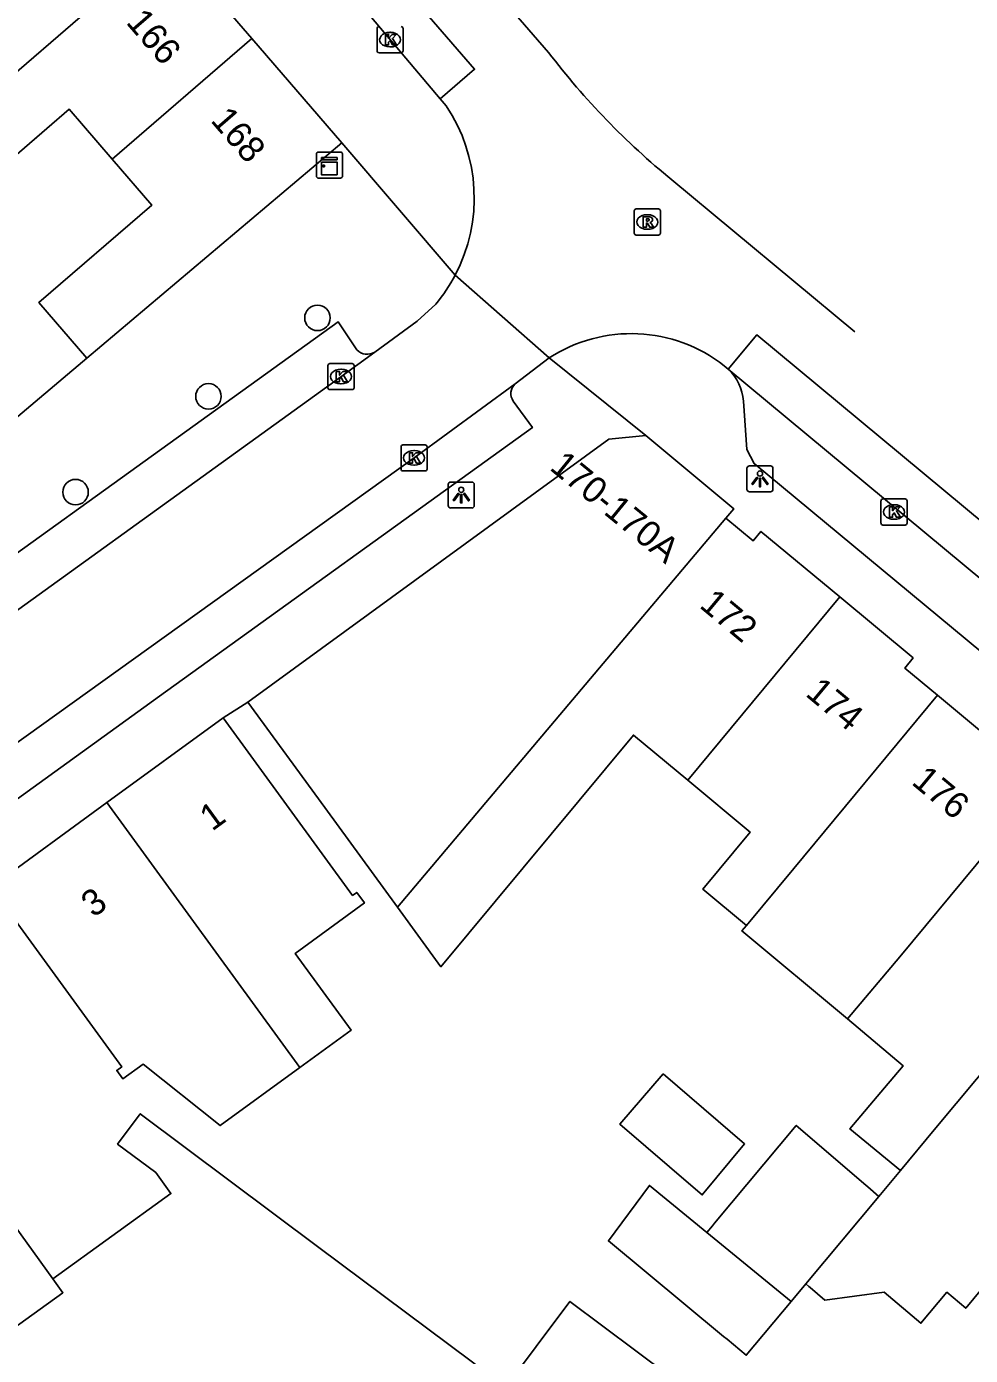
# Model space of a CAD drawing. Extents: x 161882 to 162509, y 381687 to 382379.
# Drawn here: x 162311.3 to 162347.5, y 381930 to 381980.9 of the extents above; entities that cross this region are included whole.
import ezdxf

# ---------------------------------------------------------------- set-up
doc = ezdxf.new("R2010")
doc.units = 0
for name, color, linetype in [('IMGEO_Boom', 7, 'Continuous'), ('IMGEO_Kast', 7, 'Continuous'), ('IMGEO_Kolk', 7, 'Continuous'), ('IMGEO_Lichtpunt', 7, 'Continuous'), ('IMGEO_Muur', 7, 'Continuous'), ('IMGEO_Pand', 7, 'Continuous'), ('IMGEO_Pand_nummerreeks', 7, 'Continuous'), ('IMGEO_Rijbaan_lokaal_gesloten', 7, 'Continuous'), ('IMGEO_Rijbaan_lokaal_open', 7, 'Continuous'), ('IMGEO_Rioolput', 7, 'Continuous'), ('IMGEO_Voetpad_open', 7, 'Continuous')]:
    doc.layers.add(name, color=color, linetype=linetype)

msp = doc.modelspace()

# ---------------------------------------------------------------- linework, layer by layer
at = {"layer": 'IMGEO_Boom'}
for centre in [(162322.501, 381969.752), (162318.322, 381966.743), (162313.226, 381963.073)]:
    msp.add_circle(centre, 0.489, dxfattribs=at)
at = {"layer": 'IMGEO_Kast'}
for p, q in [((162322.46, 381975.185), (162322.46, 381976.026)), ((162322.46, 381976.026), (162322.46, 381975.185)), ((162322.535, 381976.11), (162323.376, 381976.11)), ((162323.376, 381976.11), (162322.535, 381976.11)), ((162323.46, 381976.035), (162323.46, 381975.194)), ((162323.46, 381975.194), (162323.46, 381976.035)), ((162323.385, 381975.11), (162322.544, 381975.11)), ((162322.544, 381975.11), (162323.385, 381975.11))]:
    msp.add_line(p, q, dxfattribs=at)
for points in [[(162322.655, 381975.9), (162323.255, 381975.9), (162323.255, 381975.815), (162322.655, 381975.815), (162322.655, 381975.9)], [(162322.655, 381975.725), (162323.255, 381975.725), (162323.255, 381975.236), (162322.655, 381975.236), (162322.655, 381975.725)]]:
    msp.add_lwpolyline(points, dxfattribs=at)
msp.add_circle((162322.739, 381975.574), 0.0377, dxfattribs=at)
for centre, start, end in [((162322.538, 381976.032), 92.4484, 184.2845), ((162322.538, 381976.032), 92.4484, 184.2845), ((162323.382, 381976.032), 2.4484, 94.2845), ((162323.382, 381976.032), 2.4484, 94.2845), ((162322.538, 381975.188), 182.4484, 274.2845), ((162322.538, 381975.188), 182.4484, 274.2845), ((162323.382, 381975.188), 272.4484, 4.2845), ((162323.382, 381975.188), 272.4484, 4.2845)]:
    msp.add_arc(centre, 0.0779, start, end, dxfattribs=at)
at = {"layer": 'IMGEO_Kolk'}
for p, q in [((162324.785, 381979.992), (162324.785, 381980.844)), ((162325.786, 381980.844), (162325.786, 381979.992)), ((162325.273, 381980.698), (162325.298, 381980.698)), ((162325.712, 381979.918), (162324.86, 381979.918)), ((162325.296, 381980.138), (162325.271, 381980.138)), ((162322.903, 381967.077), (162322.903, 381967.929)), ((162322.978, 381968.003), (162323.83, 381968.003)), ((162323.391, 381967.783), (162323.416, 381967.783)), ((162323.904, 381967.929), (162323.904, 381967.077)), ((162323.414, 381967.223), (162323.389, 381967.223)), ((162323.83, 381967.003), (162322.978, 381967.003)), ((162325.704, 381963.959), (162325.704, 381964.811)), ((162325.779, 381964.885), (162326.631, 381964.885)), ((162326.192, 381964.665), (162326.217, 381964.665)), ((162326.705, 381964.811), (162326.705, 381963.959)), ((162326.215, 381964.105), (162326.19, 381964.105)), ((162326.631, 381963.885), (162325.779, 381963.885)), ((162344.107, 381961.886), (162344.107, 381962.738)), ((162344.182, 381962.812), (162345.034, 381962.812)), ((162344.595, 381962.592), (162344.62, 381962.592)), ((162345.108, 381962.738), (162345.108, 381961.886)), ((162344.618, 381962.032), (162344.593, 381962.032)), ((162345.034, 381961.812), (162344.182, 381961.812))]:
    msp.add_line(p, q, dxfattribs=at)
for points in [[(162324.785, 381979.992), (162324.785, 381980.844)], [(162325.786, 381980.844), (162325.786, 381979.992)], [(162325.106, 381980.618), (162325.229, 381980.618), (162325.229, 381980.467), (162325.359, 381980.618), (162325.523, 381980.618), (162325.377, 381980.467), (162325.53, 381980.218), (162325.378, 381980.218), (162325.293, 381980.382), (162325.229, 381980.315), (162325.229, 381980.218), (162325.106, 381980.218), (162325.106, 381980.618)], [(162325.712, 381979.918), (162324.86, 381979.918)], [(162322.903, 381967.077), (162322.903, 381967.929)], [(162322.978, 381968.003), (162323.83, 381968.003)], [(162323.224, 381967.703), (162323.347, 381967.703), (162323.347, 381967.552), (162323.477, 381967.703), (162323.641, 381967.703), (162323.495, 381967.552), (162323.648, 381967.303), (162323.496, 381967.303), (162323.411, 381967.467), (162323.347, 381967.4), (162323.347, 381967.303), (162323.224, 381967.303), (162323.224, 381967.703)], [(162323.904, 381967.929), (162323.904, 381967.077)], [(162323.83, 381967.003), (162322.978, 381967.003)], [(162325.704, 381963.959), (162325.704, 381964.811)], [(162325.779, 381964.885), (162326.631, 381964.885)], [(162326.025, 381964.585), (162326.148, 381964.585), (162326.148, 381964.434), (162326.278, 381964.585), (162326.442, 381964.585), (162326.296, 381964.434), (162326.449, 381964.185), (162326.297, 381964.185), (162326.212, 381964.349), (162326.148, 381964.282), (162326.148, 381964.185), (162326.025, 381964.185), (162326.025, 381964.585)], [(162326.705, 381964.811), (162326.705, 381963.959)], [(162326.631, 381963.885), (162325.779, 381963.885)], [(162344.107, 381961.886), (162344.107, 381962.738)], [(162344.182, 381962.812), (162345.034, 381962.812)], [(162344.428, 381962.512), (162344.551, 381962.512), (162344.551, 381962.361), (162344.681, 381962.512), (162344.845, 381962.512), (162344.699, 381962.361), (162344.852, 381962.112), (162344.7, 381962.112), (162344.615, 381962.276), (162344.551, 381962.209), (162344.551, 381962.112), (162344.428, 381962.112), (162344.428, 381962.512)], [(162345.108, 381962.738), (162345.108, 381961.886)], [(162345.034, 381961.812), (162344.182, 381961.812)]]:
    msp.add_lwpolyline(points, dxfattribs=at)
for centre, start, end in [((162324.862, 381980.842), 91.552, 178.448), ((162324.862, 381980.842), 91.552, 178.448), ((162325.71, 381980.842), 1.552, 88.448), ((162325.71, 381980.842), 1.552, 88.448), ((162324.862, 381979.994), 181.552, 268.448), ((162324.862, 381979.994), 181.552, 268.448), ((162325.71, 381979.994), 271.552, 358.448), ((162325.71, 381979.994), 271.552, 358.448), ((162322.98, 381967.927), 91.552, 178.448), ((162322.98, 381967.927), 91.552, 178.448), ((162323.828, 381967.927), 1.552, 88.448), ((162323.828, 381967.927), 1.552, 88.448), ((162322.98, 381967.079), 181.552, 268.448), ((162322.98, 381967.079), 181.552, 268.448), ((162323.828, 381967.079), 271.552, 358.448), ((162323.828, 381967.079), 271.552, 358.448), ((162325.781, 381964.809), 91.552, 178.448), ((162325.781, 381964.809), 91.552, 178.448), ((162326.629, 381964.809), 1.552, 88.448), ((162326.629, 381964.809), 1.552, 88.448), ((162325.781, 381963.961), 181.552, 268.448), ((162325.781, 381963.961), 181.552, 268.448), ((162326.629, 381963.961), 271.552, 358.448), ((162326.629, 381963.961), 271.552, 358.448), ((162344.184, 381962.736), 91.552, 178.448), ((162344.184, 381962.736), 91.552, 178.448), ((162345.032, 381962.736), 1.552, 88.448), ((162345.032, 381962.736), 1.552, 88.448), ((162344.184, 381961.888), 181.552, 268.448), ((162344.184, 381961.888), 181.552, 268.448), ((162345.032, 381961.888), 271.552, 358.448), ((162345.032, 381961.888), 271.552, 358.448)]:
    msp.add_arc(centre, 0.0765, start, end, dxfattribs=at)
for centre, major_axis, ratio, start_param, end_param in [((162325.272, 381980.418), (-0.387, 0.002), 0.722429, 4.712389, 7.853982), ((162325.297, 381980.418), (-0.39, 0.002), 0.717154, 1.570796, 4.712389), ((162323.39, 381967.503), (-0.387, 0.002), 0.722429, 4.712389, 7.853982), ((162323.415, 381967.503), (-0.39, 0.002), 0.717154, 1.570796, 4.712389), ((162326.191, 381964.385), (-0.387, 0.002), 0.722429, 4.712389, 7.853982), ((162326.216, 381964.385), (-0.39, 0.002), 0.717154, 1.570796, 4.712389), ((162344.594, 381962.312), (-0.387, 0.002), 0.722429, 4.712389, 7.853982), ((162344.619, 381962.312), (-0.39, 0.002), 0.717154, 1.570796, 4.712389)]:
    msp.add_ellipse(centre, major_axis=major_axis, ratio=ratio, start_param=start_param, end_param=end_param, dxfattribs=at)
at = {"layer": 'IMGEO_Lichtpunt'}
for p, q in [((162339.87, 381964.082), (162339.062, 381964.082)), ((162339.87, 381964.082), (162339.062, 381964.082)), ((162338.968, 381963.987), (162338.968, 381963.18)), ((162338.968, 381963.987), (162338.968, 381963.18)), ((162339.964, 381963.18), (162339.964, 381963.987)), ((162339.964, 381963.18), (162339.964, 381963.987)), ((162327.515, 381963.367), (162327.515, 381962.56)), ((162327.515, 381963.367), (162327.515, 381962.56)), ((162328.417, 381963.462), (162327.609, 381963.462)), ((162328.417, 381963.462), (162327.609, 381963.462)), ((162328.511, 381962.56), (162328.511, 381963.367)), ((162328.511, 381962.56), (162328.511, 381963.367)), ((162339.062, 381963.086), (162339.87, 381963.086)), ((162339.062, 381963.086), (162339.87, 381963.086)), ((162327.609, 381962.466), (162328.417, 381962.466)), ((162327.609, 381962.466), (162328.417, 381962.466))]:
    msp.add_line(p, q, dxfattribs=at)
for points in [[(162339.342, 381963.651), (162339.381, 381963.623), (162339.193, 381963.361), (162339.155, 381963.388), (162339.342, 381963.651)], [(162339.444, 381963.603), (162339.491, 381963.603), (162339.491, 381963.281), (162339.444, 381963.281), (162339.444, 381963.603)], [(162339.554, 381963.623), (162339.592, 381963.65), (162339.779, 381963.388), (162339.74, 381963.36), (162339.554, 381963.623)], [(162327.889, 381963.031), (162327.928, 381963.003), (162327.74, 381962.741), (162327.702, 381962.768), (162327.889, 381963.031)], [(162328.101, 381963.003), (162328.139, 381963.03), (162328.326, 381962.768), (162328.287, 381962.74), (162328.101, 381963.003)], [(162327.991, 381962.983), (162328.038, 381962.983), (162328.038, 381962.661), (162327.991, 381962.661), (162327.991, 381962.983)]]:
    msp.add_lwpolyline(points, dxfattribs=at)
for centre in [(162339.467, 381963.785), (162328.014, 381963.165)]:
    msp.add_circle(centre, 0.0994, dxfattribs=at)
for centre, start, end in [((162339.062, 381963.987), 90, 180), ((162339.062, 381963.987), 90, 180), ((162339.87, 381963.987), 0, 90), ((162339.87, 381963.987), 0, 90), ((162327.609, 381963.367), 90, 180), ((162327.609, 381963.367), 90, 180), ((162328.417, 381963.367), 0, 90), ((162328.417, 381963.367), 0, 90), ((162339.062, 381963.18), 180, 270), ((162339.062, 381963.18), 180, 270), ((162339.87, 381963.18), 270, 0), ((162339.87, 381963.18), 270, 360), ((162327.609, 381962.56), 180, 270), ((162327.609, 381962.56), 180, 270), ((162328.417, 381962.56), 270, 0), ((162328.417, 381962.56), 270, 360)]:
    msp.add_arc(centre, 0.0946, start, end, dxfattribs=at)
at = {"layer": 'IMGEO_Muur'}
msp.add_lwpolyline([(162319.836, 381955.026), (162318.885, 381954.422)], dxfattribs=at)
at = {"layer": 'IMGEO_Pand'}
for points in [[(162307.124, 381975.871), (162316.763, 381984.19)], [(162316.763, 381984.19), (162319.982, 381980.464)], [(162319.982, 381980.464), (162314.626, 381975.841)], [(162319.982, 381980.464), (162323.438, 381976.466)], [(162314.626, 381975.841), (162312.982, 381977.748), (162308.692, 381974.051), (162307.124, 381975.871)], [(162323.438, 381976.466), (162313.652, 381968.207)], [(162313.652, 381968.207), (162311.813, 381970.336), (162316.149, 381974.073), (162314.626, 381975.841)], [(162319.836, 381955.026), (162333.67, 381965.108), (162335.091, 381965.239)], [(162335.091, 381965.239), (162338.463, 381962.436), (162338.16, 381962.07)], [(162338.16, 381962.07), (162325.568, 381947.162)], [(162338.16, 381962.07), (162339.2, 381961.206), (162339.504, 381961.571), (162342.53, 381959.056)], [(162342.53, 381959.056), (162336.696, 381952.029)], [(162342.53, 381959.056), (162345.34, 381956.72), (162345.017, 381956.332), (162346.276, 381955.285)], [(162319.836, 381955.026), (162322.781, 381950.985), (162325.568, 381947.162)], [(162346.276, 381955.285), (162340.765, 381948.647), (162338.95, 381946.461)], [(162346.276, 381955.285), (162349.959, 381952.224), (162350.302, 381952.636), (162350.687, 381952.316)], [(162314.43, 381951.175), (162318.885, 381954.422)], [(162321.829, 381941.021), (162323.794, 381942.453), (162321.65, 381945.395), (162324.299, 381947.326), (162324.004, 381947.731), (162323.846, 381947.616), (162318.885, 381954.422)], [(162325.568, 381947.162), (162327.231, 381944.881), (162334.613, 381953.761), (162336.696, 381952.029)], [(162342.825, 381942.887), (162344.833, 381945.265), (162350.687, 381952.316)], [(162336.696, 381952.029), (162339.085, 381950.043), (162337.27, 381947.857), (162338.95, 381946.461)], [(162309.976, 381947.929), (162314.43, 381951.175)], [(162321.829, 381941.021), (162314.43, 381951.175)], [(162344.855, 381937.071), (162346.152, 381938.625), (162354.393, 381948.496)], [(162309.976, 381947.929), (162314.995, 381941.042), (162314.807, 381940.905), (162315.043, 381940.58), (162315.816, 381941.143), (162318.769, 381938.791), (162321.829, 381941.021)], [(162338.95, 381946.461), (162338.777, 381946.252), (162342.825, 381942.887)], [(162312.352, 381932.924), (162307.362, 381939.85), (162304.439, 381943.906)], [(162342.825, 381942.887), (162344.956, 381941.087), (162344.241, 381940.239), (162342.915, 381938.666), (162344.855, 381937.071)], [(162335.751, 381940.774), (162334.095, 381938.844), (162336.989, 381936.36), (162337.252, 381936.134), (162338.877, 381938.091), (162335.751, 381940.774)], [(162329.705, 381928.752), (162328.389, 381929.759), (162322.559, 381934.122), (162315.708, 381939.25), (162314.837, 381938.086), (162316.301, 381936.99), (162316.88, 381936.187), (162312.352, 381932.924)], [(162344.025, 381936.078), (162343.599, 381936.444), (162343.525, 381936.508), (162340.856, 381938.798), (162337.725, 381935.047), (162337.647, 381934.954), (162337.428, 381934.692)], [(162344.855, 381937.071), (162344.025, 381936.078)], [(162337.428, 381934.692), (162335.226, 381936.497), (162333.659, 381934.374), (162338.071, 381930.712), (162338.205, 381930.601), (162338.942, 381929.99), (162340.658, 381932.045)], [(162344.025, 381936.078), (162341.223, 381932.722)], [(162337.428, 381934.692), (162340.658, 381932.045)], [(162341.223, 381932.722), (162341.335, 381932.628), (162341.385, 381932.586), (162341.955, 381932.104), (162344.231, 381932.406), (162345.64, 381931.216), (162346.632, 381932.405), (162347.358, 381931.792), (162349.38, 381934.229)], [(162306.732, 381928.061), (162312.738, 381932.388), (162312.352, 381932.924)], [(162340.658, 381932.045), (162340.727, 381932.127), (162341.223, 381932.722)], [(162334.722, 381924.911), (162336.256, 381926.959), (162337.238, 381928.272), (162332.18, 381932.056), (162330.883, 381930.326), (162329.705, 381928.752)]]:
    msp.add_lwpolyline(points, dxfattribs=at)
at = {"layer": 'IMGEO_Rijbaan_lokaal_gesloten'}
for points in [[(162208.443, 382099.25), (162241.416, 382072.435), (162262.315, 382053.78), (162275.851, 382040.075), (162276.287, 382039.572), (162328.522, 381979.28), (162327.205, 381978.154)], [(162320.032, 381992.987), (162331.362, 381979.927)], [(162327.205, 381978.154), (162324.227, 381981.677), (162324.071, 381981.856)], [(162336.093, 381975.038), (162343.107, 381969.212)], [(162338.251, 381967.787), (162339.352, 381969.106), (162376.704, 381938.084)], [(162361.697, 381948.318), (162338.251, 381967.787)]]:
    msp.add_lwpolyline(points, dxfattribs=at)
msp.add_arc((162354.43, 381997.516), 29.009, 217.325, 230.7931, dxfattribs=at)
at = {"layer": 'IMGEO_Rijbaan_lokaal_open'}
for points in [[(162327.205, 381978.154), (162327.438, 381977.88)], [(162327.78, 381971.392), (162331.386, 381968.216)], [(162327.035, 381970.281), (162326.325, 381969.625), (162324.695, 381968.444)], [(162324.695, 381968.444), (162323.401, 381967.499), (162305.988, 381954.94), (162294.59, 381946.712)], [(162330.083, 381967.219), (162331.386, 381968.216)], [(162338.096, 381967.916), (162338.251, 381967.787)], [(162306.701, 381950.389), (162308.296, 381951.542), (162326.207, 381964.389), (162330.083, 381967.219)]]:
    msp.add_lwpolyline(points, dxfattribs=at)
for centre, radius, start, end in [((162322.164, 381974.349), 6.347, 332.2321, 33.8027), ((162322.169, 381974.349), 6.343, 320.1026, 332.2084), ((162334.531, 381963.379), 5.77, 51.8456, 123.0345)]:
    msp.add_arc(centre, radius, start, end, dxfattribs=at)
at = {"layer": 'IMGEO_Rioolput'}
for p, q in [((162334.649, 381973.002), (162334.649, 381973.854)), ((162334.724, 381973.928), (162335.576, 381973.928)), ((162335.137, 381973.708), (162335.162, 381973.708)), ((162335.65, 381973.854), (162335.65, 381973.002)), ((162335.576, 381972.928), (162334.724, 381972.928)), ((162335.16, 381973.148), (162335.135, 381973.148))]:
    msp.add_line(p, q, dxfattribs=at)
for points in [[(162334.649, 381973.002), (162334.649, 381973.854)], [(162334.724, 381973.928), (162335.576, 381973.928)], [(162335.65, 381973.854), (162335.65, 381973.002)], [(162335.238, 381973.626), (162334.986, 381973.628), (162334.986, 381973.228)], [(162334.986, 381973.228), (162335.11, 381973.228), (162335.11, 381973.39), (162335.121, 381973.39)], [(162335.164, 381973.547), (162335.11, 381973.547), (162335.11, 381973.466)], [(162335.11, 381973.466), (162335.162, 381973.466)], [(162335.168, 381973.361), (162335.239, 381973.228), (162335.379, 381973.228), (162335.314, 381973.354)], [(162335.576, 381972.928), (162334.724, 381972.928)]]:
    msp.add_lwpolyline(points, dxfattribs=at)
for centre, radius, start, end in [((162334.726, 381973.852), 0.0765, 91.552, 178.448), ((162334.726, 381973.852), 0.0765, 91.552, 178.448), ((162335.574, 381973.852), 0.0765, 1.552, 88.448), ((162335.574, 381973.852), 0.0765, 1.552, 88.448), ((162335.12, 381973.337), 0.0533, 26.0293, 88.6989), ((162335.146, 381973.655), 0.19, 274.7715, 282.9687), ((162335.17, 381973.451), 0.0964, 77.0061, 93.1865), ((162335.184, 381973.508), 0.0378, 276.6634, 79.6772), ((162335.237, 381973.516), 0.109, 350.3612, 89.416), ((162335.235, 381973.516), 0.112, 277.5842, 350.9817), ((162335.219, 381973.301), 0.108, 29.5134, 73.7905), ((162334.726, 381973.004), 0.0765, 181.552, 268.448), ((162334.726, 381973.004), 0.0765, 181.552, 268.448), ((162335.574, 381973.004), 0.0765, 271.552, 358.448), ((162335.574, 381973.004), 0.0765, 271.552, 358.448)]:
    msp.add_arc(centre, radius, start, end, dxfattribs=at)
for centre, major_axis, ratio, start_param, end_param in [((162335.136, 381973.428), (-0.387, 0.002), 0.722429, 4.712389, 7.853982), ((162335.161, 381973.428), (-0.39, 0.002), 0.717154, 1.570796, 4.712389)]:
    msp.add_ellipse(centre, major_axis=major_axis, ratio=ratio, start_param=start_param, end_param=end_param, dxfattribs=at)
at = {"layer": 'IMGEO_Voetpad_open'}
for points in [[(162327.78, 381971.392), (162323.438, 381976.466)], [(162282.623, 381938.734), (162281.904, 381939.805), (162323.289, 381969.605), (162324.01, 381968.526)], [(162310.436, 381965.492), (162313.652, 381968.207)], [(162331.386, 381968.216), (162335.091, 381965.239)], [(162330.009, 381966.566), (162330.743, 381965.549), (162316.447, 381955.247), (162308.029, 381949.187), (162307.31, 381950.215)], [(162357.753, 381948.82), (162339.248, 381964.171), (162338.968, 381964.709), (162338.833, 381966.563)], [(162318.885, 381954.422), (162319.836, 381955.026)]]:
    msp.add_lwpolyline(points, dxfattribs=at)
for centre, radius, start, end in [((162324.401, 381968.887), 0.532, 222.7637, 303.5837), ((162337.002, 381966.443), 1.835, 3.7588, 47.1024), ((162330.391, 381966.853), 0.478, 130.1213, 216.948)]:
    msp.add_arc(centre, radius, start, end, dxfattribs=at)

# ---------------------------------------------------------------- texts
at = {"layer": 'IMGEO_Pand_nummerreeks'}
for s, rotation, p in [('166', 310.7957, (162315.128, 381981.066)), ('168', 310.7944, (162318.372, 381977.305)), ('170-170A', 320.7679, (162331.36, 381963.961)), ('172', 320.2064, (162337.103, 381958.682)), ('174', 320.2081, (162341.171, 381955.292)), ('176', 320.2081, (162345.237, 381951.906)), ('1', 36.0851, (162318.459, 381950.053)), ('3', 36.0851, (162313.912, 381946.74))]:
    msp.add_text(s, height=1, rotation=rotation, dxfattribs=at).set_placement(p)

doc.saveas('drawing.dxf')
